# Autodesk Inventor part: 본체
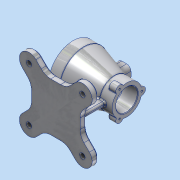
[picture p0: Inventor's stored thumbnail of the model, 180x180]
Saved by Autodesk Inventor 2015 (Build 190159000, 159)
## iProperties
Created: 2018-03
Part Number: 본체
Material: 알루미늄 6061
Document SubType Name: Modeling
Designer: SCD-A05
Density: 2.7 g/cm^3
Appearance: 알루미늄 - 평지
Author: SCD-A05
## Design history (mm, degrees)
sketch "스케치1"
  geometry: L1 (0, 0)-(100, 0); L2 (0, 35)-(0, 45); L3 (0, 45)-(20, 45); L4 (20, 45)-(77, 27.5); L5 (77, 27.5)-(100, 27.5); L6 (100, 27.5)-(100, 20); L7 (100, 20)-(70, 20); L8 (70, 20)-(70, 26); L9 (70, 26)-(23, 26); L10 (23, 26)-(23, 35); L11 (23, 35)-(0, 35); 2 further points
  constraints: 22 end point, 7 perpendicular, 2 midpoint, 2 vertical alignment, 1 horizontal, 1 parallel, 1 vertical
  dimensions: "d0" = 100 distance of L1.start L1.end; "d1" = 70 diameter of L11 L1; "d2" = 52 diameter of L9 L1; "d3" = 40 diameter of L7 L1; "d4" = 90 diameter of L3 L1; "d5" = 30 distance between parallel lines of L6 L8; "d6" = 47 distance between parallel lines of L10 L8; "d7" = 20 distance of L2.end L3.end; "d8" = 77 distance from line of L2 L4.end; "d9" = 55 diameter of L5 L1
revolve "회전1" sketch "스케치1" stored, may be unused: angle "d10" = 90 deg
sketch "스케치2"
  geometry: 2 further points
  constraints: 1 vertical alignment
  dimensions: "d11" = 40 distance of point (0, 0) point (0, 40)
hole "구멍1" sketch "스케치2" at (0, 40) diameter "d12" = 3.242; stored, may be unused: countersink angle "d16" = 90 deg, drill point angle "d18" = 118 deg; dims "d13" = 9, "d14" = 4, "d15" = 2, "d17" = 11
sketch "스케치3"
  geometry: C1 r 7 at (0, 27.5); C2 r 45 at (0, 0) reference; C3 r 7 at (-23.816, -13.75); C4 r 7 at (23.816, -13.75); 2 further points
  constraints: 3 centre point, 2 vertical alignment, 8 other
  dimensions: "d22" = 14 diameter of C1; "d25" = 360 deg dimension on C2.centre C1.centre (derived)
extrude "돌출1" join sketch "스케치3" distance "d27" = 15; taper "d28" = 0 deg
hole "구멍2" diameter "d31" = 3.242; stored, may be unused: countersink angle "d35" = 90 deg, drill point angle "d37" = 118 deg; dims "d29" = 10, "d30" = 10, "d32" = 9, "d33" = 4, "d34" = 2, "d36" = 11
hole "구멍3" diameter "d40" = 3.242; stored, may be unused: countersink angle "d44" = 90 deg, drill point angle "d46" = 118 deg; dims "d38" = 10, "d39" = 10, "d41" = 9, "d42" = 4, "d43" = 2, "d45" = 11
hole "구멍4" diameter "d49" = 3.242; stored, may be unused: countersink angle "d53" = 90 deg, drill point angle "d55" = 118 deg; dims "d47" = 10, "d48" = 10, "d50" = 9, "d51" = 4, "d52" = 2, "d54" = 11
node "작업 평면1"
sketch "스케치4"
  geometry: L1 (-37.5, 12.5)-(-62.5, 12.5); L2 (-62.5, 12.5)-(-62.5, -12.5); L3 (-62.5, -12.5)-(-37.5, -12.5); L4 (-37.5, -12.5)-(-37.5, 12.5); L5 (-50, -12.5)-(-50, 12.5); L6 (0, 45)-(0, -45) reference; 1 further point
  constraints: 10 end point, 2 midpoint, 2 parallel, 1 horizontal, 1 perpendicular
  dimensions: "d57" = 25 distance between parallel lines of L1 L3; "d58" = 25 distance between parallel lines of L2 L4; "d59" = 12.5 distance from line of point (0, 0) L3; "d60" = 50 distance between parallel lines of L6 L5
extrude "돌출2" join sketch "스케치4" stored distance "d61" = 10; taper "d62" = 0 deg
sketch "스케치5"
  geometry: L1 (-42.5, 7.5)-(-57.5, 7.5); L2 (-57.5, 7.5)-(-57.5, -7.5); L3 (-57.5, -7.5)-(-42.5, -7.5); L4 (-42.5, -7.5)-(-42.5, 7.5); L5 (-50, -7.5)-(-50, 7.5); L6 (0, 45)-(0, -45) reference; 1 further point
  constraints: 10 end point, 2 midpoint, 2 parallel, 1 horizontal, 1 perpendicular
  dimensions: "d63" = 15 distance of L3.end L2.end; "d64" = 15 distance of L2.end L1.end; "d65" = 50 distance between parallel lines of L6 L5; "d66" = 7.5 distance from line of point (0, 0) L3
extrude "돌출3" cut sketch "스케치5" distance "d67" = 27.25; taper "d68" = 0 deg
node "작업 평면2"
sketch "스케치6"
  geometry: L1 (-50, 0)-(-50, 77.225); L2 (-50, 0)-(-99.497, 49.497); L3 (-69.544, -45)-(-30.456, -45); L4 (-5, -19.544)-(-5, 19.544); L5 (-30.456, 45)-(-69.544, 45); L6 (-95, 19.544)-(-95, -19.544); L7 (-161.576, -111.576)-(-71.576, -21.576); L8 (61.576, -111.576)-(-161.576, 111.576); L9 (-50, 0)-(-36.63, 13.37); L10 (-50, 0)-(-51.605, 1.605); L11 (-50, 0)-(-179.348, -129.348); L12 (-13.23, 62.225)-(-30.456, 45); L13 (12.225, 36.77)-(-5, 19.544); L14 (-86.77, 62.225)-(-69.544, 45); L15 (-112.225, 36.77)-(-95, 19.544); L16 (-95, -19.544)-(-112.225, -36.77); L17 (-69.544, -45)-(-86.77, -62.225); L18 (-5, -19.544)-(12.225, -36.77); L19 (-30.456, -45)-(-13.23, -62.225); L20 (-50, 0)-(-50, 35.239); L21 (-50, 0)-(-202.697, 0); L22 (0, 45)-(0, -45) reference; A1 r 18 centre (-99.497, 49.497) between (-86.77, 62.225) and (-110.483, 35.239); A2 r 70 centre (-50, 0) between (-99.497, 49.497) and (-0.503, 49.497); A3 r 18 centre (-0.503, 49.497) between (12.225, 36.77) and (-13.23, 62.225); A4 r 18 centre (-0.503, -49.497) between (-13.23, -62.225) and (12.225, -36.77); A5 r 18 centre (-99.497, -49.497) between (-112.225, -36.77) and (-86.77, -62.225); 2 further points
  constraints: 42 end point, 14 point on circle, 10 parallel, 8 tangent, 5 centre point, 5 point on line, 3 midpoint, 2 horizontal, 1 horizontal alignment, 1 perpendicular, 1 vertical, 3 other
  dimensions: "d70" = 36 diameter of A1; "d71" = 140 diameter of A2; "d72" = 45 deg angle of L1 L2; "d73" = 90 distance between parallel lines of L6 L4; "d74" = 90 distance between parallel lines of L3 L5; "d75" = 18 radius of A3; "d76" = 45 deg angle of L1 L9; "d77" = 45 deg angle of L1 L11; "d78" = 45 deg angle of L1 L10; "d79" = 18 radius of A4; "d80" = 18 radius of A5; "d81" = 45 distance from line of L4 L1.start; "d82" = 45 distance from line of L3 L1.start; "d83" = 50 distance from line of L1.start L22
extrude "돌출4" join sketch "스케치6" distance "d84" = 12; taper "d85" = 0 deg
hole "구멍5" diameter "d88" = 10; stored, may be unused: countersink angle "d92" = 90 deg, drill point angle "d94" = 118 deg; dims "d86" = 10, "d87" = 10, "d89" = 6, "d90" = 4, "d91" = 2, "d93" = 8
hole "구멍6" diameter "d97" = 10; stored, may be unused: countersink angle "d101" = 90 deg, drill point angle "d103" = 118 deg; dims "d95" = 10, "d96" = 10, "d98" = 6, "d99" = 4, "d100" = 2, "d102" = 8
hole "구멍7" diameter "d106" = 10; stored, may be unused: countersink angle "d110" = 90 deg, drill point angle "d112" = 118 deg; dims "d104" = 10, "d105" = 10, "d107" = 6, "d108" = 4, "d109" = 2, "d111" = 8
hole "구멍8" diameter "d115" = 10; stored, may be unused: countersink angle "d119" = 90 deg, drill point angle "d121" = 118 deg; dims "d113" = 10, "d114" = 10, "d116" = 6, "d117" = 4, "d118" = 2, "d120" = 8
sketch "스케치7"
  geometry: L1 (87, -25)-(87, -70); L2 (30.456, -82)-(30.456, -70) reference; L3 (87, -70)-(13, -70); L4 (13, -70)-(13, -38); L5 (62.5, 45)-(37.5, 45) reference; L6 (50, 45)-(50, -184.319); L7 (13, -38)-(77, -25); L8 (77, -25)-(87, -25); L9 (77, -27.5)-(77, 27.5) reference; L10 (86.77, -70)-(69.544, -70) reference; 1 further point
  constraints: 12 end point, 3 perpendicular, 1 collinear, 1 midpoint, 1 parallel, 1 point on line, 1 vertical
  dimensions: "d122" = 37 distance between parallel lines of L6 L1; "d123" = 37 distance between parallel lines of L4 L6; "d126" = 45 distance between parallel lines of L3 L8; "d127" = 32 distance of L3.end L4.end
extrude "돌출5" join sketch "스케치7" stored distance "d124" = 8; taper "d125" = 0 deg
node "작업 평면3"
sketch "스케치8"
  geometry: L1 (-24, -70)-(-20.25, -27.137); L2 (-20.25, -27.137)-(20.25, -27.137); L3 (20.25, -27.137)-(24, -70); L4 (24, -70)-(-24, -70); L5 (19.544, -70)-(-19.544, -70) reference; L6 (67.497, -70)-(36.77, -70) reference; L7 (-36.77, -70)-(-67.497, -70) reference; 3 further points
  constraints: 8 end point, 1 collinear, 1 horizontal, 1 parallel
  dimensions: "d129" = 95 deg angle of L6 L3; "d130" = 95 deg angle of L7 L1; "d131" = 24 horizontal distance of point (0, 0) L1.start; "d132" = 24 horizontal distance of point (0, 0) L3.end; "d133" = 40.5 distance of L1.end L2.end
extrude "돌출6" join sketch "스케치8" stored distance "d134" = 8; taper "d135" = 0 deg
fillet "모깎기1" dims "d136" = 25
chamfer "모따기1" distance "d137" = 3; stored, may be unused: second distance "d138" = 2, angle "d139" = 45 deg
fillet "모깎기2" dims "d140" = 3
fillet "모깎기3" dims "d141" = 3
fillet "모깎기4" dims "d142" = 1
fillet "모깎기5" dims "d143" = 8
fillet "모깎기6" dims "d144" = 3
fillet "모깎기7" dims "d145" = 1
chamfer "모따기2" distance "d146" = 1; stored, may be unused: second distance "d147" = 2, angle "d148" = 45 deg
chamfer "모따기3" distance "d149" = 1; stored, may be unused: second distance "d150" = 2, angle "d151" = 45 deg
fillet "모깎기8" dims "d152" = 3
fillet "모깎기9" dims "d153" = 3
fillet "모깎기10" dims "d154" = 3
sketch "스케치9"
  geometry: L1 (33.408, -32.598)-(66.592, -32.598); L2 (66.592, -32.598)-(66.592, -37.402); L3 (66.592, -37.402)-(33.408, -37.402); L4 (33.408, -37.402)-(33.408, -32.598); L5 (33.408, -35)-(66.592, -35); L6 (50, -32.598)-(50, -37.402); L7 (95, -9.189)-(95, 9.189) reference; 1 further point
  constraints: 4 end point, 4 midpoint, 2 other
  dimensions: "d155" = 45 distance between parallel lines of L7 L6; "d157" = 35 distance from line of point (0, 0) L5
feature "엠보싱1" sketch "스케치9" dims "d0" = 100, "d1" = 70, "d2" = 52, "d3" = 40, "d4" = 90, "d5" = 30, "d6" = 47, "d7" = 20, "d8" = 77, "d9" = 55, "d158" = 0.5, "d159" = 0
node "솔리드1"
pattern_circular "원형 패턴1" dims angle "d20" = 360 deg
other parameters: "d56" = 45, "d69" = -82
